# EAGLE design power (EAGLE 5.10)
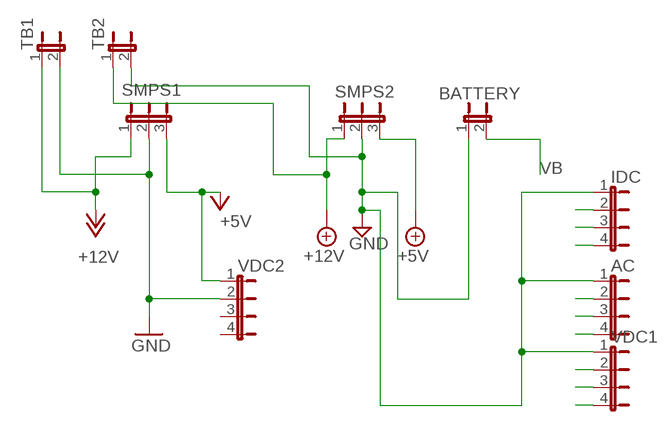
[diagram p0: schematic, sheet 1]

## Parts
AC  JP4E  [JP4]
BATTERY  JP1E  [JP1]
IDC  JP4E  [JP4]
SMPS1  JP2E  [JP2]
SMPS2  JP2E  [JP2]
TB1  JP1E  [JP1]
TB2  JP1E  [JP1]
VDC1  JP4E  [JP4]
VDC2  JP4E  [JP4]

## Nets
+5V/1: AC.2 IDC.2 SMPS2.3 VDC1.2 ; supply symbol labelled +5V
+5V/2: SMPS1.3 VDC2.1 ; supply symbol labelled +5V
+12V/1: SMPS2.1 TB2.1 ; supply symbol labelled +12V
+12V/2: SMPS1.1 TB1.1 ; supply symbol labelled +12V
GND1: AC.1 BATTERY.1 IDC.1 SMPS2.2 TB2.2 VDC1.1 ; supply symbol labelled GND
GND2: SMPS1.2 TB1.2 VDC2.2 ; supply symbol labelled GND
SCL: AC.4 IDC.4 VDC1.4
SDA: AC.3 IDC.3 VDC1.3
VB: BATTERY.2
Unconnected: VDC2.3 VDC2.4

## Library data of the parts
AC IDC VDC1 VDC2 = jumper:JP4E: JUMPER
BATTERY TB1 TB2 = jumper:JP1E: JUMPER
SMPS1 SMPS2 = jumper:JP2E: JUMPER

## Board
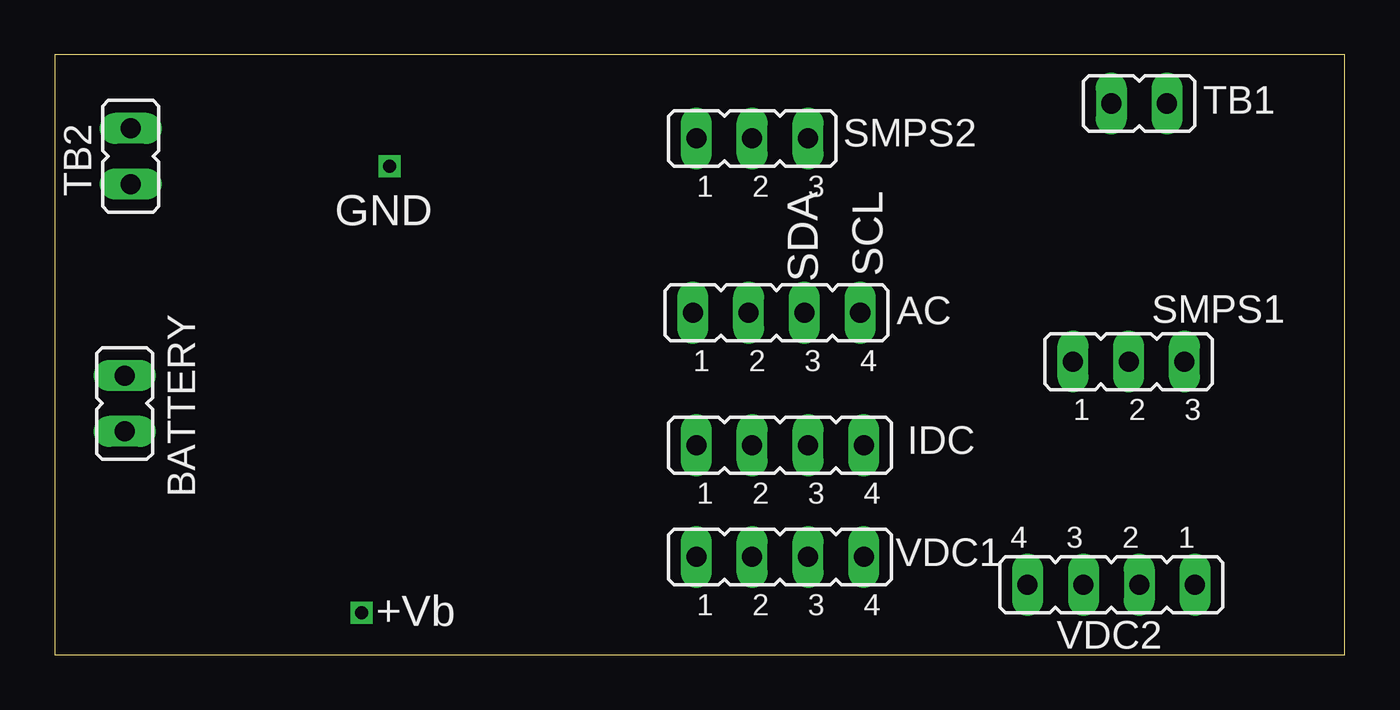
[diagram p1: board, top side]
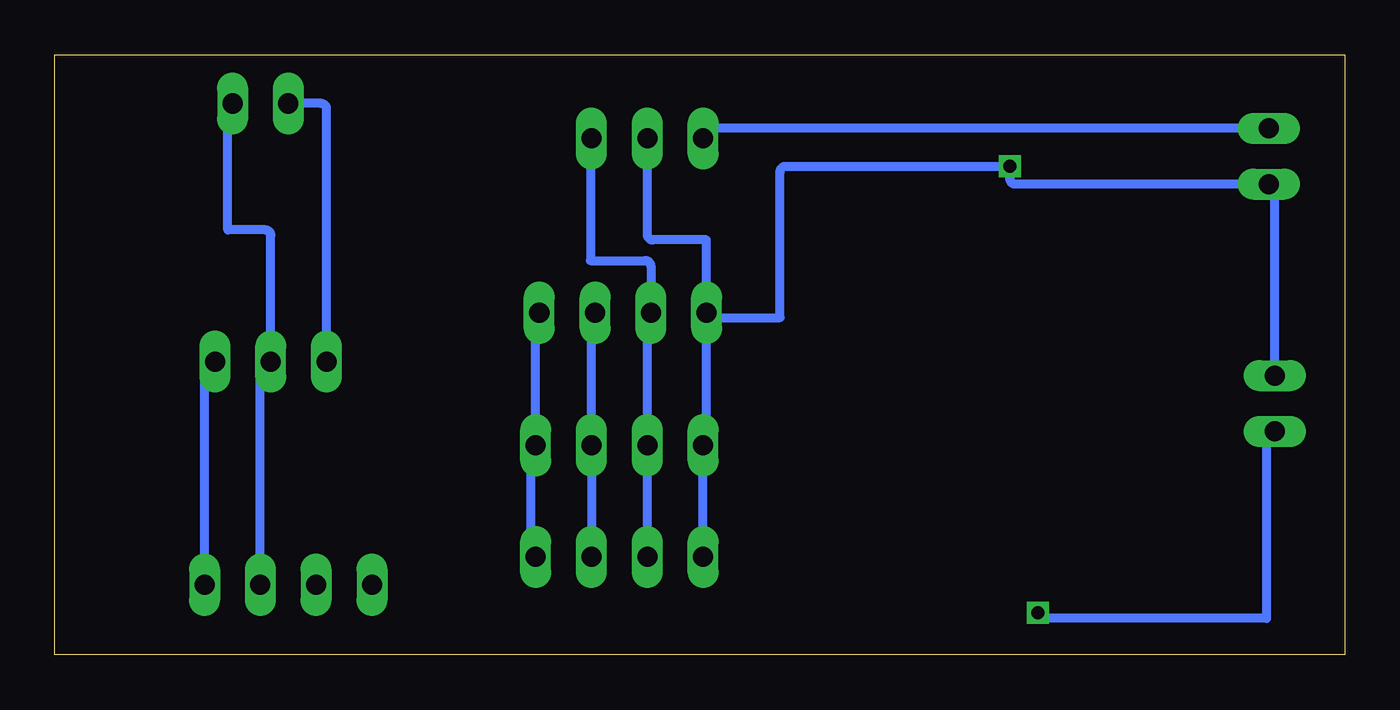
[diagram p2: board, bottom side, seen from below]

Size 58.73 x 27.3 mm. Coordinates in mm from the lower left corner, seen from the top.
Outline: 0,0 58.73,0 58.73,27.3 0,27.3 0,0
Copper layers (1*16): Top 0.035mm / dielectric 1.5mm / Bottom 0.035mm
Design rules "default": minimum track width 10mil, minimum drill 24mil, track to track 8mil, track to pad 8mil, pad to pad 8mil, via to via 8mil, smd to smd 8mil, copper to edge 40mil, drill to drill 8mil, minimum pad ring 10mil, minimum via ring 8mil, stop-mask expansion 4mil, vias tented up to drill 0mil, thermal gap 10mil

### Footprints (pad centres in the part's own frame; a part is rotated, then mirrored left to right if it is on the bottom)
JP4 = drill 0.914 long: 1 -3.81,0; 2 -1.27,0; 3 1.27,0; 4 3.81,0
JP1 = drill 0.914 long: 1 0,-1.27; 2 0,1.27
JP2 = drill 0.914 long: 1 -2.54,0; 2 0,0; 3 2.54,0

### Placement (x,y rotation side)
AC  32.86,15.55 0 top
BATTERY  3.17,11.43 180 top
IDC  33.02,9.53 0 top
SMPS1  48.9,13.34 0 top
SMPS2  31.75,23.5 0 top
TB1  49.37,25.09 270 top
TB2  3.45,22.68 180 top
VDC1  33.02,4.45 0 top
VDC2  48.1,3.17 180 top

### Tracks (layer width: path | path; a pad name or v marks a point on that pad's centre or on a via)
+5V/1
  Bottom 0.406: VDC1.2 IDC.2 31.75,15.39 arc90 AC.2 31.59,17.68 arc-90 31.84,17.93 34.34,17.93 34.34,23.44 arc90 SMPS2.3
+5V/2
  Bottom 0.406: SMPS1.3 51.66,13.34 arc-90 51.91,13.08 VDC2.1
+12V/1
  Bottom 0.406: TB2.1 28.96,23.95 arc-90 29.21,23.7 SMPS2.1
+12V/2
  Bottom 0.406: TB1.1 46.61,25.09 arc90 46.35,24.83 SMPS1.1
GND1  (via drill 0.6)
  Bottom 0.406: VDC1.1 IDC.1 arc-90 29.05,9.69 AC.1 | AC.1 arc90 29.06,15.56 29.06,18.87 31.5,18.87 arc90 31.75,19.13 SMPS2.2 | AC.1 arc-90 28.84,15.34 25.7,15.34 25.7,21.97 arc90 25.45,22.23 v15.24,22.23 15.24,21.67 arc-90 14.99,21.41 TB2.2 3.43,21.41 arc90 3.17,21.16 BATTERY.1
GND2
  Bottom 0.406: TB1.2 arc-90 50.85,24.87 50.85,19.33 49.15,19.33 arc90 48.9,19.07 SMPS1.2 49.12,13.34 arc-90 49.37,13.08 VDC2.2
SCL
  Bottom 0.406: AC.4 arc-90 36.83,15.39 IDC.4 arc-90 37.03,9.32 37.03,3.94 arc-90 36.83,4.14 VDC1.4
SDA
  Bottom 0.406: AC.3 arc-90 34.29,15.39 IDC.3 VDC1.3
VB  (via drill 0.6)
  Bottom 0.406: BATTERY.2 3.3,10.16 arc-90 3.56,9.91 3.56,1.65 13.72,1.65 arc90 v13.97,1.91

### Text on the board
tPlace: GND | SDA | SCL | +Vb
